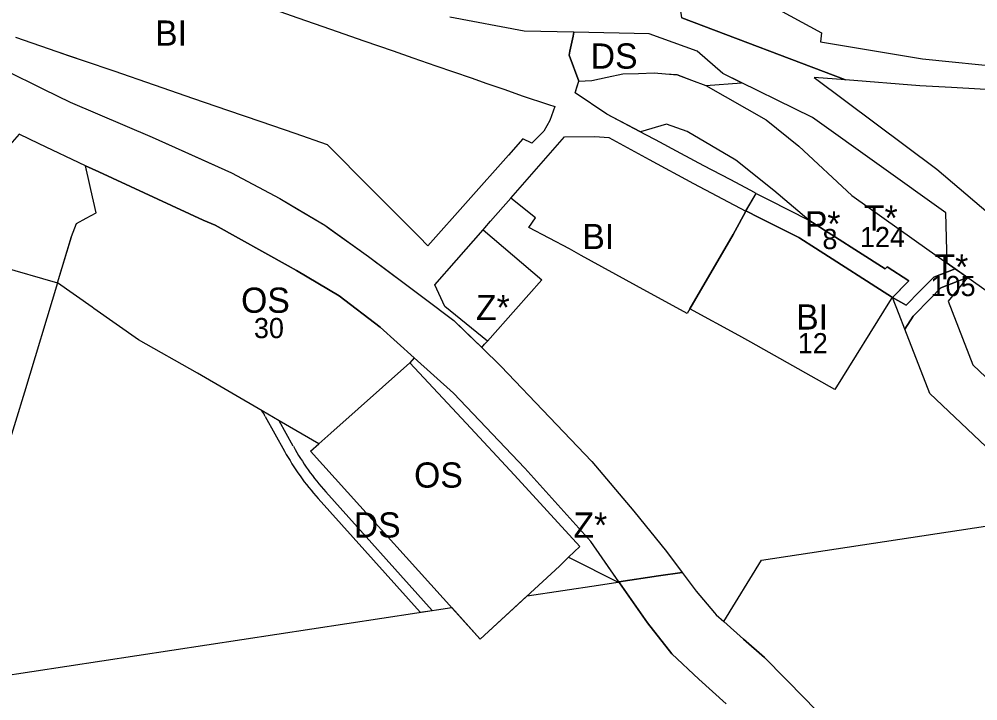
# Model space of a CAD drawing. Extents: x -521621 to -516769, y -1190068 to -1185078.
# Drawn here: x -518605.8 to -518225.8, y -1187581.5 to -1187311.1 of the extents above; entities that cross this region are included whole.
import ezdxf

# ---------------------------------------------------------------- set-up
doc = ezdxf.new("R2010")
doc.units = 0
for name, color, linetype in [('bydleni_n', 7, 'Continuous'), ('bydleni_s', 7, 'Continuous'), ('fpl_id', 7, 'Continuous'), ('s_zelen_s', 7, 'Continuous'), ('v_infrastr_n', 7, 'Continuous'), ('v_infrastr_s', 7, 'Continuous'), ('voda_s', 7, 'Continuous')]:
    doc.layers.add(name, color=color, linetype=linetype)

msp = doc.modelspace()

# ---------------------------------------------------------------- linework, layer by layer
at = {"layer": 'bydleni_n'}
for points in [[(-518320.5, -1187436.54), (-518339.96, -1187426.08), (-518322.79, -1187396.6), (-518320.4, -1187392.2), (-518317.7, -1187387.23), (-518317.69, -1187387.22), (-518312.35, -1187389.9), (-518296.71, -1187397.76), (-518296.32, -1187398.01)], [(-518296.32, -1187398.01), (-518290.11, -1187401.98), (-518259.54, -1187421.48), (-518260.14, -1187422.08), (-518282.4, -1187457.96), (-518315.79, -1187439.19), (-518320.5, -1187436.54)]]:
    msp.add_lwpolyline(points, dxfattribs=at)
at = {"layer": 'bydleni_s'}
msp.add_line((-518361.11, -1187416.86), (-518383.04, -1187404.83), dxfattribs=at)
for points in [[(-518522.71, -1187301.06), (-518514.92, -1187303.77), (-518509.16, -1187305.77), (-518495.4, -1187310.55), (-518482.42, -1187315.06), (-518469.15, -1187319.68)], [(-518590.7, -1187324.08), (-518607.2, -1187318.4)], [(-518469.15, -1187319.68), (-518457.5, -1187323.73), (-518449.7, -1187326.44)], [(-518579.86, -1187327.8), (-518586.21, -1187325.62), (-518590.7, -1187324.08)], [(-518568.19, -1187331.81), (-518579.86, -1187327.8)], [(-518449.7, -1187326.44), (-518440.62, -1187329.59), (-518426.63, -1187334.46), (-518420.38, -1187336.63), (-518413.28, -1187339.1)], [(-518552.1, -1187337.35), (-518568.19, -1187331.81)], [(-518536.59, -1187342.69), (-518552.1, -1187337.35)], [(-518413.28, -1187339.1), (-518406.41, -1187341.54)], [(-518523.13, -1187347.32), (-518536.59, -1187342.69)], [(-518406.41, -1187341.54), (-518396.01, -1187344.92), (-518393.43, -1187345.76)], [(-518509.81, -1187351.91), (-518523.13, -1187347.32)], [(-518393.43, -1187345.76), (-518395.43, -1187351.34), (-518397.76, -1187355.51), (-518402.53, -1187360.28), (-518406.07, -1187358.61)], [(-518496.43, -1187356.51), (-518509.81, -1187351.91)], [(-518483.56, -1187360.94), (-518496.43, -1187356.51)], [(-518406.07, -1187358.61), (-518411.85, -1187365.12)], [(-518383.04, -1187404.83), (-518387.67, -1187402.29), (-518403.75, -1187393.75), (-518401.08, -1187389.94), (-518410.85, -1187382.12), (-518389.56, -1187357.84)], [(-518389.56, -1187357.84), (-518377.59, -1187357.73), (-518372.05, -1187358.12)], [(-518372.05, -1187358.12), (-518356.09, -1187366.82), (-518338.45, -1187376.31)], [(-518477.7, -1187366.84), (-518483.56, -1187360.94)], [(-518472.15, -1187372.44), (-518477.7, -1187366.84)], [(-518411.85, -1187365.12), (-518443.76, -1187401.07), (-518447.29, -1187397.51)], [(-518467.13, -1187377.5), (-518472.15, -1187372.44)], [(-518458.89, -1187385.81), (-518467.13, -1187377.5)], [(-518338.45, -1187376.31), (-518317.7, -1187387.23), (-518320.4, -1187392.2), (-518322.79, -1187396.6)], [(-518451.1, -1187393.66), (-518458.89, -1187385.81)], [(-518447.29, -1187397.51), (-518451.1, -1187393.66)], [(-518322.79, -1187396.6), (-518339.96, -1187426.08), (-518341.01, -1187427.89), (-518361.11, -1187416.86)]]:
    msp.add_lwpolyline(points, dxfattribs=at)
at = {"layer": 's_zelen_s'}
for points in [[(-518432.45, -1187406.74), (-518421.85, -1187394.65), (-518398.55, -1187414.52), (-518408.9, -1187426.17)], [(-518408.9, -1187426.17), (-518420.15, -1187438.82), (-518437, -1187425.12), (-518440.99, -1187416.48), (-518432.45, -1187406.74)], [(-518433.61, -1187459.42), (-518449.21, -1187445.4), (-518450.9, -1187447.42), (-518428.6, -1187471.34), (-518409.38, -1187492.02), (-518383.53, -1187520.34), (-518388.01, -1187524.58), (-518367.87, -1187534.73), (-518379.14, -1187518.37), (-518405.37, -1187489.2), (-518433.61, -1187459.42)]]:
    msp.add_lwpolyline(points, dxfattribs=at)
at = {"layer": 'v_infrastr_n'}
for points in [[(-518306.58, -1187379.13), (-518321.66, -1187367.12), (-518340.92, -1187355.7), (-518349.21, -1187352.83), (-518359.49, -1187355.88), (-518372.79, -1187348.81), (-518385.35, -1187340.38), (-518383.99, -1187335.74), (-518381.4, -1187335.61), (-518378.81, -1187335.49), (-518372.64, -1187334.19), (-518366.47, -1187332.88), (-518360.28, -1187332.66), (-518354.09, -1187332.43), (-518349.55, -1187332.78), (-518346.44, -1187333.02), (-518345.02, -1187333.13), (-518344.51, -1187333.32), (-518339.29, -1187335.27), (-518333.55, -1187337.4), (-518309.69, -1187351.08), (-518296.66, -1187361.46)], [(-518296.66, -1187361.46), (-518275.69, -1187381.09)], [(-518275.69, -1187381.09), (-518245.02, -1187402.86), (-518237.86, -1187407.94), (-518234.69, -1187410.19), (-518243.19, -1187413.46), (-518248.69, -1187419.02), (-518254.21, -1187424.61), (-518259.54, -1187421.48), (-518253.87, -1187415.68), (-518253.11, -1187414.91), (-518261.72, -1187409.41), (-518262.44, -1187410.14), (-518292.75, -1187390.8), (-518306.58, -1187379.13)], [(-518248.69, -1187419.02), (-518243.19, -1187413.46), (-518234.69, -1187410.19), (-518232.24, -1187411.93), (-518229.8, -1187413.66), (-518240.39, -1187417.74), (-518244.42, -1187421.82)], [(-518259.54, -1187421.48), (-518254.21, -1187424.61), (-518248.69, -1187419.02)], [(-518244.42, -1187421.82), (-518251.44, -1187428.93), (-518254.65, -1187434.11), (-518256.92, -1187428.27), (-518259.54, -1187421.48)], [(-518325.58, -1187582.72), (-518336.39, -1187572.85), (-518347.04, -1187562.81), (-518356.76, -1187550.62), (-518367.87, -1187534.73), (-518368.12, -1187534.37), (-518352.34, -1187531.97), (-518342.96, -1187530.54), (-518337.35, -1187538.01), (-518330.21, -1187546.55), (-518329.48, -1187547.42), (-518326.5, -1187550.08), (-518318.68, -1187557.07), (-518310.35, -1187564.32), (-518294.06, -1187580.83), (-518281.02, -1187594.41)], [(-518805.65, -1187584), (-518833.12, -1187576.51), (-518739.02, -1187578.77), (-518614.79, -1187571.96), (-518434.34, -1187544.46), (-518423, -1187557.03), (-518404.48, -1187539.91), (-518376.14, -1187535.59), (-518368.47, -1187534.43), (-518367.87, -1187534.73), (-518356.76, -1187550.62), (-518347.04, -1187562.81), (-518336.39, -1187572.85), (-518325.58, -1187582.72)]]:
    msp.add_lwpolyline(points, dxfattribs=at)
for points in [[(-518574.22, -1187371.72), (-518532.84, -1187390.9), (-518528.06, -1187392.9), (-518499.19, -1187408.92), (-518495.81, -1187410.8), (-518478.98, -1187420.84), (-518462.63, -1187433.34), (-518449.21, -1187445.4), (-518450.9, -1187447.42), (-518482.3, -1187475.38), (-518487.02, -1187479.58), (-518502.69, -1187470.47), (-518509.54, -1187466.48), (-518535.16, -1187451.58), (-518558.54, -1187438.31), (-518576.17, -1187425.86), (-518576.81, -1187425.41), (-518590.56, -1187415.7), (-518585.12, -1187397.38), (-518583.11, -1187392.13), (-518579.21, -1187390.07), (-518577.26, -1187389.04), (-518575.31, -1187388.01), (-518576.35, -1187383.33), (-518577.38, -1187378.65), (-518578.42, -1187373.97), (-518579.45, -1187369.29)], [(-518262.44, -1187410.14), (-518261.72, -1187409.41), (-518253.11, -1187414.91), (-518259.54, -1187421.48), (-518290.11, -1187401.98), (-518296.32, -1187398.01), (-518296.71, -1187397.76), (-518312.35, -1187389.9), (-518317.69, -1187387.22), (-518313.58, -1187380.27), (-518308.55, -1187382.81), (-518292.75, -1187390.8)], [(-518229.8, -1187413.66), (-518237.49, -1187423.04), (-518227.74, -1187448.23), (-518191.68, -1187482.43), (-518172.9, -1187498.89), (-518165.48, -1187503.49), (-518193.17, -1187507.71), (-518205.16, -1187497.21), (-518244.77, -1187459.64), (-518254.65, -1187434.11), (-518251.44, -1187428.93), (-518244.42, -1187421.82), (-518240.39, -1187417.74)], [(-518311.51, -1187525.75), (-518193.17, -1187507.71), (-518188.48, -1187512.34), (-518115.06, -1187560.43), (-518097.49, -1187580.5), (-518072.11, -1187608.7), (-518011.34, -1187661.01), (-517958.1, -1187698.4), (-518101.98, -1187696.13), (-518223.7, -1187714.67), (-518226.7, -1187702.52), (-518231.25, -1187682.45), (-518235.88, -1187661.62), (-518237.5, -1187652.9), (-518243.14, -1187639.86), (-518253.09, -1187626.59), (-518266.52, -1187610.77), (-518267.78, -1187609.35), (-518281.02, -1187594.41), (-518294.06, -1187580.83), (-518310.35, -1187564.32), (-518318.68, -1187557.07), (-518326.5, -1187550.08)]]:
    msp.add_lwpolyline(points, close=True, dxfattribs=at)
at = {"layer": 'v_infrastr_s'}
for p, q in [((-518405.54, -1187315.9), (-518435.04, -1187310.32)), ((-518385.89, -1187316.34), (-518405.54, -1187315.9)), ((-518579.45, -1187369.29), (-518597.94, -1187360.53))]:
    msp.add_line(p, q, dxfattribs=at)
for points in [[(-518343.07, -1187310.63), (-518343.61, -1187307.03), (-518338.64, -1187305.49), (-518326.11, -1187301.38), (-518312.56, -1187302.88), (-518287.67, -1187316.52), (-518288.18, -1187320.19)], [(-518495.4, -1187310.55), (-518482.42, -1187315.06), (-518469.15, -1187319.68), (-518457.5, -1187323.73), (-518449.7, -1187326.44), (-518440.62, -1187329.59), (-518426.63, -1187334.46), (-518420.38, -1187336.63), (-518413.28, -1187339.1), (-518406.41, -1187341.54), (-518396.01, -1187344.92)], [(-518405.54, -1187315.9), (-518435.04, -1187310.32)], [(-518248.78, -1187337.53), (-518278.17, -1187335.2), (-518343.07, -1187310.63)], [(-518343.07, -1187310.63), (-518278.17, -1187335.2)], [(-518385.89, -1187316.34), (-518405.54, -1187315.9)], [(-518339.29, -1187335.27), (-518333.55, -1187337.4), (-518319.47, -1187336.35), (-518326.8, -1187332.75), (-518336.97, -1187323.88), (-518356.01, -1187317), (-518385.89, -1187316.34), (-518386.21, -1187317.82), (-518387.49, -1187323.78), (-518387.83, -1187325.37), (-518383.99, -1187335.74), (-518381.4, -1187335.61), (-518378.81, -1187335.49), (-518372.64, -1187334.19), (-518366.47, -1187332.88), (-518360.28, -1187332.66), (-518354.09, -1187332.43), (-518349.55, -1187332.78), (-518345.02, -1187333.13), (-518339.29, -1187335.27)], [(-518386.21, -1187317.82), (-518385.89, -1187316.34)], [(-518356.01, -1187317), (-518385.89, -1187316.34)], [(-518336.97, -1187323.88), (-518356.01, -1187317)], [(-518393.43, -1187345.76), (-518395.43, -1187351.34), (-518397.76, -1187355.51), (-518402.53, -1187360.28), (-518406.07, -1187358.61), (-518411.85, -1187365.12), (-518443.76, -1187401.07), (-518447.29, -1187397.51), (-518451.1, -1187393.66), (-518458.89, -1187385.81), (-518467.13, -1187377.5), (-518472.15, -1187372.44), (-518477.7, -1187366.84), (-518483.56, -1187360.94), (-518496.43, -1187356.51), (-518509.81, -1187351.91), (-518523.13, -1187347.32), (-518536.59, -1187342.69), (-518552.1, -1187337.35), (-518568.19, -1187331.81), (-518579.86, -1187327.8), (-518590.7, -1187324.08), (-518607.2, -1187318.4)], [(-518387.83, -1187325.37), (-518387.49, -1187323.78), (-518386.21, -1187317.82)], [(-518288.18, -1187320.19), (-518247.68, -1187326.9), (-518213.77, -1187330.31), (-518166.56, -1187334.49), (-518090, -1187341.45)], [(-518326.8, -1187332.75), (-518336.97, -1187323.88)], [(-518383.99, -1187335.74), (-518387.83, -1187325.37)], [(-518611.68, -1187331.23), (-518596.14, -1187338.88), (-518585.54, -1187344.09)], [(-518291.32, -1187350.19), (-518326.8, -1187332.75)], [(-518384.67, -1187338.06), (-518383.99, -1187335.74)], [(-518278.17, -1187335.2), (-518290.69, -1187334.21)], [(-518290.69, -1187334.21), (-518241.96, -1187370.69)], [(-518385.35, -1187340.38), (-518384.97, -1187339.09)], [(-518372.79, -1187348.81), (-518385.35, -1187340.38)], [(-518384.97, -1187339.09), (-518384.67, -1187338.06)], [(-518236.16, -1187338.27), (-518248.78, -1187337.53)], [(-517903.26, -1187502.14), (-517921.14, -1187489.42), (-517950.34, -1187468.33), (-518034.34, -1187396.85), (-518051.08, -1187371.3), (-518053.59, -1187367.46), (-518063.05, -1187362.09), (-518067.11, -1187359.78), (-518081.32, -1187351.71), (-518113.74, -1187347.57), (-518173.8, -1187344.62), (-518199.87, -1187340.38), (-518236.16, -1187338.27)], [(-518585.54, -1187344.09), (-518553.06, -1187357.95)], [(-518396.01, -1187344.92), (-518393.43, -1187345.76)], [(-518357.43, -1187356.98), (-518372.79, -1187348.81)], [(-518238.4, -1187387.96), (-518291.32, -1187350.19)], [(-518597.94, -1187360.53), (-518605.81, -1187356.8), (-518628.1, -1187382.14), (-518641.6, -1187398.11), (-518647.62, -1187418.94), (-518656.03, -1187447.42)], [(-518553.06, -1187357.95), (-518530.95, -1187367.91)], [(-518410.85, -1187382.12), (-518389.56, -1187357.84), (-518377.59, -1187357.73), (-518372.05, -1187358.12)], [(-518372.05, -1187358.12), (-518356.09, -1187366.82), (-518338.45, -1187376.31), (-518317.7, -1187387.23)], [(-518353.56, -1187359.03), (-518357.43, -1187356.98)], [(-518343.5, -1187364.38), (-518353.56, -1187359.03)], [(-518334.34, -1187369.25), (-518343.5, -1187364.38)], [(-518578.54, -1187373.39), (-518579.45, -1187369.29)], [(-518530.95, -1187367.91), (-518521.58, -1187372.14)], [(-518323.96, -1187374.76), (-518334.34, -1187369.25)], [(-518241.96, -1187370.69), (-518200.31, -1187406.02)], [(-518578.42, -1187373.97), (-518578.54, -1187373.39)], [(-518575.31, -1187388.01), (-518576.35, -1187383.33), (-518577.38, -1187378.65), (-518578.42, -1187373.97)], [(-518521.58, -1187372.14), (-518502.51, -1187382.22)], [(-518315.77, -1187379.11), (-518323.96, -1187374.76)], [(-518502.51, -1187382.22), (-518495.19, -1187386.59)], [(-518418.91, -1187391.31), (-518410.85, -1187382.12)], [(-518317.7, -1187387.23), (-518313.58, -1187380.27)], [(-518313.58, -1187380.27), (-518315.77, -1187379.11)], [(-518579.21, -1187390.07), (-518577.26, -1187389.04), (-518575.31, -1187388.01)], [(-518495.19, -1187386.59), (-518484.67, -1187392.87)], [(-518237.86, -1187407.94), (-518238.4, -1187387.96)], [(-518585.12, -1187397.38), (-518583.11, -1187392.13)], [(-518583.11, -1187392.13), (-518579.21, -1187390.07)], [(-518484.67, -1187392.87), (-518482.56, -1187394.37)], [(-518421.17, -1187393.88), (-518418.91, -1187391.31)], [(-518590.56, -1187415.7), (-518585.13, -1187397.42)], [(-518585.13, -1187397.42), (-518585.12, -1187397.38)], [(-518482.56, -1187394.37), (-518467.26, -1187405.28)], [(-518420.15, -1187438.82), (-518437, -1187425.12), (-518440.99, -1187416.48), (-518432.45, -1187406.74), (-518421.85, -1187394.65)], [(-518421.85, -1187394.65), (-518421.17, -1187393.88)], [(-518659.8, -1187483.07), (-518654.57, -1187465.94), (-518645.46, -1187432.53), (-518636.51, -1187402.51), (-518590.56, -1187415.7), (-518603.76, -1187459.07), (-518614.48, -1187493.95), (-518621.5, -1187517.1), (-518665.87, -1187503.51), (-518662.85, -1187494.33)], [(-518636.51, -1187402.51), (-518590.56, -1187415.7)], [(-518467.26, -1187405.28), (-518463.45, -1187408.14)], [(-518463.45, -1187408.14), (-518462.74, -1187408.68)], [(-518462.74, -1187408.68), (-518445.26, -1187421.79), (-518433.48, -1187430.64)], [(-518220.14, -1187420.52), (-518237.86, -1187407.94)], [(-518433.48, -1187430.64), (-518427.95, -1187436.01)], [(-518427.95, -1187436.01), (-518422.42, -1187441.37)], [(-518421.29, -1187440.09), (-518420.15, -1187438.82)], [(-518422.42, -1187441.37), (-518421.29, -1187440.09)], [(-518497.12, -1187480.56), (-518502.69, -1187470.47), (-518509.54, -1187466.48)], [(-518508.22, -1187468.72), (-518500.62, -1187482.49)], [(-518446.81, -1187546.36), (-518442.09, -1187545.64), (-518484.28, -1187498.62)], [(-518487.26, -1187501.29), (-518446.81, -1187546.36)]]:
    msp.add_lwpolyline(points, dxfattribs=at)
msp.add_lwpolyline([(-518490.29, -1187482.49), (-518487.02, -1187479.58), (-518482.3, -1187475.38), (-518450.9, -1187447.42), (-518428.6, -1187471.34), (-518409.38, -1187492.02), (-518383.53, -1187520.34), (-518388.01, -1187524.58), (-518391.64, -1187528.05), (-518423, -1187557.03)], close=True, dxfattribs=at)
for centre, radius, start, end in [((-518550.24, -1187491.93), 48, 28.9162, 32.0228), ((-518411.33, -1187433.17), 98, 208.9163, 221.8979), ((-518411.33, -1187433.17), 102, 208.9163, 221.8979)]:
    msp.add_arc(centre, radius, start, end, dxfattribs=at)
at = {"layer": 'voda_s'}
for points in [[(-518611.68, -1187331.23), (-518596.14, -1187338.88), (-518585.54, -1187344.09), (-518553.06, -1187357.95), (-518521.58, -1187372.14), (-518502.51, -1187382.22), (-518484.67, -1187392.87), (-518467.26, -1187405.28), (-518445.26, -1187421.79), (-518433.48, -1187430.64), (-518422.42, -1187441.37), (-518414.69, -1187448.87), (-518395.52, -1187469.02), (-518378.78, -1187486.62), (-518362.1, -1187506.29), (-518349.16, -1187522.27), (-518342.96, -1187530.54)], [(-518597.94, -1187360.53), (-518605.81, -1187356.8)], [(-518579.45, -1187369.29), (-518597.94, -1187360.53)], [(-518368.12, -1187534.37), (-518379.14, -1187518.37), (-518405.37, -1187489.2), (-518433.61, -1187459.42), (-518449.21, -1187445.4), (-518462.63, -1187433.34), (-518478.98, -1187420.84), (-518495.81, -1187410.8), (-518499.19, -1187408.92), (-518528.06, -1187392.9), (-518532.84, -1187390.9), (-518574.22, -1187371.72), (-518579.45, -1187369.29)], [(-518342.96, -1187530.54), (-518352.34, -1187531.97), (-518368.12, -1187534.37)]]:
    msp.add_lwpolyline(points, dxfattribs=at)

# ---------------------------------------------------------------- texts
at = {"layer": 'bydleni_n'}
msp.add_text('BI', height=10, dxfattribs=at).set_placement((-518297.77, -1187434.24))
at = {"layer": 'bydleni_s'}
for p in [(-518551.91, -1187321.65), (-518382.53, -1187402.34)]:
    msp.add_text('BI', height=10, dxfattribs=at).set_placement(p)
at = {"layer": 'fpl_id'}
for s, p in [('124', (-518272.49, -1187401.54)), ('8', (-518287.36, -1187402.35)), ('105', (-518244.5, -1187420.97)), ('30', (-518512.74, -1187437.65)), ('12', (-518297.13, -1187443.66))]:
    msp.add_text(s, height=8, dxfattribs=at).set_placement(p)
at = {"layer": 's_zelen_s'}
for p in [(-518424.7, -1187430.48), (-518386.06, -1187516.8)]:
    msp.add_text('Z*', height=10, dxfattribs=at).set_placement(p)
at = {"layer": 'v_infrastr_n'}
for s, p in [('T*', (-518270.89, -1187394.96)), ('P*', (-518294.32, -1187397.3)), ('T*', (-518242.9, -1187414.39)), ('OS', (-518517.83, -1187427.6))]:
    msp.add_text(s, height=10, dxfattribs=at).set_placement(p)
at = {"layer": 'v_infrastr_s'}
for s, p in [('DS', (-518379.22, -1187330.76)), ('OS', (-518449.25, -1187496.95)), ('DS', (-518473.16, -1187516.74))]:
    msp.add_text(s, height=10, dxfattribs=at).set_placement(p)

doc.saveas('drawing.dxf')
